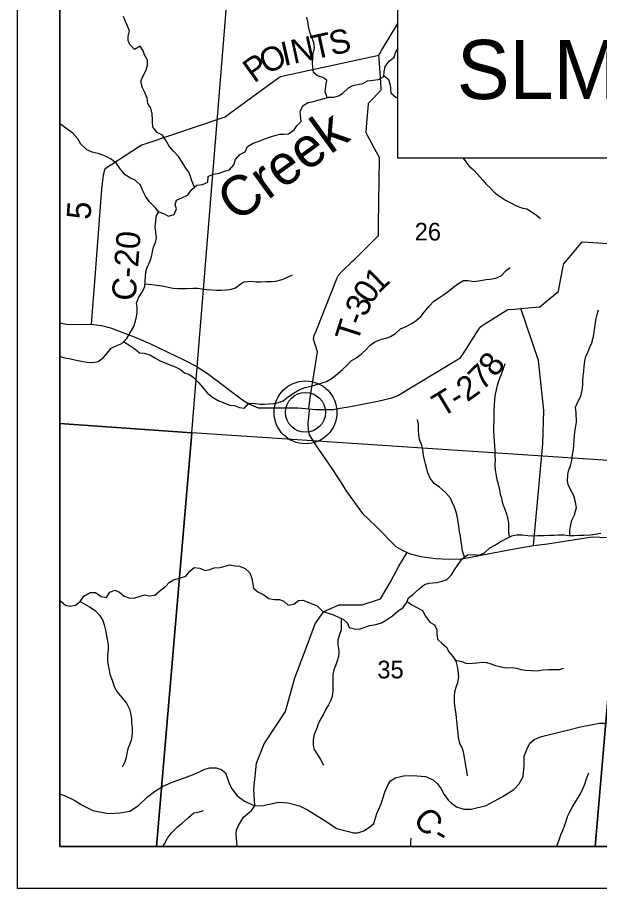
# Model space of a CAD drawing. Extents: x 0 to 34, y 0 to 22.
# Drawn here: x 23.417 to 24.795, y 14 to 16.062 of the extents above; entities that cross this region are included whole.
import ezdxf

# ---------------------------------------------------------------- set-up
doc = ezdxf.new("R2010")
doc.units = 0
for name, color, linetype in [('GM_X_Corporation', 7, 'Continuous'), ('GM_X_County_Road', 7, 'Continuous'), ('GM_X_County_Road_Text', 7, 'Continuous'), ('GM_X_Minor_River', 7, 'Continuous'), ('GM_X_Minor_River_Text', 7, 'Continuous'), ('GM_X_Section_Text', 7, 'Continuous'), ('GM_X_Township_Road', 7, 'Continuous'), ('GM_X_Township_Road_Text', 7, 'Continuous'), ('GM_X_Unincorporated', 7, 'Continuous'), ('GM_X_Unincorporated_Location', 7, 'Continuous'), ('SH_Data', 7, 'Continuous'), ('SH_Text', 7, 'Continuous')]:
    doc.layers.add(name, color=color, linetype=linetype)

msp = doc.modelspace()

# ---------------------------------------------------------------- linework, layer by layer
at = {"layer": 'GM_X_Corporation'}
for points in [[(26.1825, 18.4635), (26.1926, 18.5708), (26.207, 18.8068), (26.2271, 19.0168), (26.2277, 19.0233), (26.2281, 19.0286), (26.3029, 19.931), (25.7174, 19.9778), (25.482, 19.99), (25.2916, 20.0037), (25.117, 20.0172), (24.3889, 20.0736), (24.2296, 20.084), (23.8215, 20.1257), (23.5167, 20.1476), (23.5167, 14.1), (25.8273, 14.1), (25.8671, 14.5774), (25.9626, 15.7291)], [(24.9264, 15.7291), (24.8621, 15.0105), (23.8295, 15.0789), (23.9154, 16.1379), (24.3169, 16.1005)]]:
    msp.add_lwpolyline(points, dxfattribs=at)
for points in [[(23.5167, 16.1675), (23.5167, 15.1011), (23.8295, 15.0789), (23.9154, 16.1379)], [(23.5167, 15.1011), (23.5167, 14.1), (23.7459, 14.1), (23.8295, 15.0789)], [(23.7459, 14.1), (24.7842, 14.1), (24.8621, 15.0105), (23.8295, 15.0789)], [(24.7842, 14.1), (25.8293, 14.1), (25.8914, 14.8743), (25.8953, 14.9265), (24.8621, 15.0105)]]:
    msp.add_lwpolyline(points, close=True, dxfattribs=at)
at = {"layer": 'GM_X_County_Road'}
for points in [[(23.5923, 15.3361), (23.601, 15.4477), (23.6163, 15.6558), (23.6201, 15.69), (23.6247, 15.7045), (23.703, 15.7557), (23.7112, 15.7608), (23.7211, 15.7641), (23.9015, 15.8249), (23.9085, 15.8272), (23.9187, 15.8347), (24.0319, 15.9175), (24.0394, 15.9229), (24.0499, 15.9252), (24.2654, 15.9717), (24.2719, 15.9731), (24.2788, 15.9845), (24.3169, 16.0477)], [(23.5167, 15.3391), (23.5326, 15.3365), (23.5694, 15.3358), (23.5923, 15.3361)], [(23.5923, 15.3361), (23.6159, 15.3333), (23.6371, 15.3278), (23.6726, 15.3142), (23.6969, 15.3048), (23.7319, 15.2896), (23.8105, 15.2515), (23.8394, 15.2367), (23.8666, 15.2197), (23.9492, 15.1571), (23.9641, 15.1475), (23.9863, 15.1379), (24.0815, 15.1384), (24.1063, 15.1357), (24.1072, 15.1311), (24.1044, 15.102), (24.1048, 15.0862), (24.107, 15.0744), (24.124, 15.0483), (24.1609, 14.9942), (24.1843, 14.9585), (24.194, 14.9426), (24.2338, 14.8883), (24.2478, 14.8747), (24.267, 14.8565), (24.3124, 14.8097), (24.3292, 14.8003), (24.3395, 14.7958), (24.3475, 14.7923), (24.3709, 14.7863), (24.406, 14.7811), (24.4369, 14.7802), (24.4687, 14.7806), (24.4967, 14.7858), (24.5884, 14.8036), (24.6381, 14.8121), (24.6714, 14.8158), (24.7773, 14.8327), (24.8494, 14.8299)], [(23.5167, 14.2243), (23.5293, 14.2198), (23.5512, 14.2096), (23.5716, 14.1965), (23.595, 14.1848), (23.6314, 14.1775), (23.6592, 14.179), (23.6825, 14.1834), (23.7029, 14.1965), (23.7248, 14.2169), (23.7409, 14.23), (23.7598, 14.2417), (23.7832, 14.2519), (23.8124, 14.2621), (23.8313, 14.2694), (23.8474, 14.2767), (23.8605, 14.2826), (23.8722, 14.2855), (23.8873, 14.2856), (23.8989, 14.2821), (23.9093, 14.2739), (23.9142, 14.2603), (23.9179, 14.2485), (23.925, 14.2355), (23.9363, 14.22), (23.954, 14.207), (23.9786, 14.1956), (23.9992, 14.1963), (24.0094, 14.1994), (24.0349, 14.2049), (24.0569, 14.2031), (24.0845, 14.1958), (24.1031, 14.1863), (24.1424, 14.1617), (24.1728, 14.1425), (24.2005, 14.1352), (24.2122, 14.1323), (24.2224, 14.1323), (24.237, 14.1367), (24.2501, 14.1455), (24.2603, 14.1542), (24.2676, 14.1775), (24.2778, 14.2009), (24.2866, 14.2286), (24.2939, 14.2461), (24.2997, 14.2549), (24.3114, 14.2622), (24.3304, 14.2666), (24.3523, 14.268), (24.3829, 14.2651), (24.4004, 14.2578), (24.4106, 14.249), (24.4194, 14.2359), (24.4267, 14.2228), (24.4369, 14.2082), (24.4442, 14.2024), (24.4559, 14.1936), (24.4734, 14.1878), (24.4909, 14.1878), (24.5259, 14.1965), (24.5638, 14.217), (24.5916, 14.2345), (24.6047, 14.2476), (24.6135, 14.2651), (24.6164, 14.2914), (24.6164, 14.3133), (24.6222, 14.3293), (24.6295, 14.3439), (24.6397, 14.3526), (24.6572, 14.3599), (24.7024, 14.371), (24.7187, 14.3753), (24.7495, 14.3827), (24.7945, 14.3913), (24.8204, 14.3919)], [(23.9368, 14.1), (23.9345, 14.1287), (23.9356, 14.139), (23.9399, 14.1496), (23.9521, 14.1687), (23.9708, 14.1852), (23.9786, 14.1956)]]:
    msp.add_lwpolyline(points, dxfattribs=at)
at = {"layer": 'GM_X_Minor_River'}
for points in [[(23.8359, 15.6609), (23.8293, 15.6759), (23.8267, 15.6857), (23.8225, 15.6964), (23.8154, 15.7059), (23.8067, 15.7195), (23.7977, 15.7328), (23.7864, 15.7458), (23.7762, 15.7579), (23.7691, 15.7705), (23.7597, 15.7838), (23.7476, 15.7903), (23.7378, 15.8017), (23.7363, 15.8115), (23.7364, 15.821), (23.736, 15.8343), (23.7323, 15.8472), (23.7255, 15.859), (23.7237, 15.8715), (23.7173, 15.8863), (23.7124, 15.8958), (23.7091, 15.9106), (23.7137, 15.9227), (23.7209, 15.9363), (23.7247, 15.9484), (23.7248, 15.9609), (23.7176, 15.9735), (23.7143, 15.9833), (23.7071, 15.9944), (23.6939, 15.9865), (23.6825, 15.9982), (23.6788, 16.0077), (23.6788, 16.0183), (23.6819, 16.0308), (23.6778, 16.0403), (23.6725, 16.0525), (23.668, 16.0646)], [(24.1496, 15.8726), (24.1452, 15.8862), (24.1464, 15.8991), (24.1494, 15.9142), (24.1396, 15.9203), (24.1272, 15.9238), (24.1173, 15.9318), (24.1159, 15.9443), (24.1152, 15.9538), (24.1148, 15.964), (24.1171, 15.9769), (24.1195, 15.9901), (24.1184, 16.0034), (24.1127, 16.0171), (24.1086, 16.0277), (24.1053, 16.041), (24.1038, 16.0531), (24.1016, 16.063)], [(23.5167, 15.2594), (23.5292, 15.2567), (23.5391, 15.2551), (23.5561, 15.2512), (23.5686, 15.2489), (23.5818, 15.2462), (23.595, 15.2454), (23.6079, 15.2476), (23.6208, 15.2574), (23.6288, 15.2673), (23.6386, 15.2794), (23.6519, 15.2857), (23.6637, 15.2903), (23.6754, 15.3023), (23.6842, 15.3175), (23.6922, 15.3303), (23.696, 15.3432), (23.6983, 15.3534), (23.6999, 15.3637), (23.6999, 15.3762), (23.6988, 15.3856), (23.7034, 15.3989), (23.7122, 15.4117), (23.7179, 15.4254), (23.7194, 15.4371), (23.7195, 15.4492), (23.721, 15.4602), (23.7241, 15.4704), (23.731, 15.486), (23.7352, 15.4988), (23.7363, 15.5083), (23.739, 15.5182), (23.7432, 15.5295), (23.7459, 15.5405), (23.7445, 15.5541), (23.7426, 15.567), (23.7442, 15.5799), (23.7454, 15.592), (23.7514, 15.6019), (23.7624, 15.598), (23.7745, 15.5916), (23.7874, 15.5957), (23.7935, 15.6089), (23.7897, 15.6184), (23.7935, 15.6301), (23.806, 15.635), (23.8189, 15.6414), (23.8292, 15.6554), (23.8417, 15.6656), (23.8546, 15.6671), (23.8671, 15.6723), (23.8683, 15.686), (23.88, 15.6916), (23.894, 15.6938), (23.9069, 15.6983), (23.919, 15.7017), (23.9293, 15.7134), (23.9327, 15.7263), (23.943, 15.7376), (23.9555, 15.7444), (23.9616, 15.7569), (23.9745, 15.7644), (23.9889, 15.7696), (23.9999, 15.7742), (24.0154, 15.7794), (24.026, 15.7832), (24.0377, 15.7861), (24.0476, 15.7861), (24.0582, 15.7872), (24.0714, 15.7962), (24.0779, 15.8061), (24.0882, 15.8163), (24.0867, 15.8311), (24.086, 15.8405), (24.0932, 15.8538), (24.105, 15.8609), (24.1178, 15.8635), (24.1277, 15.8665), (24.1428, 15.8707), (24.1531, 15.8736), (24.1659, 15.8736), (24.1765, 15.877), (24.1864, 15.8826), (24.2004, 15.8955), (24.2107, 15.9015), (24.222, 15.9037), (24.2345, 15.9056), (24.2455, 15.912), (24.2588, 15.9142), (24.2713, 15.9153), (24.2841, 15.9228), (24.2846, 15.9334), (24.2873, 15.9459), (24.2964, 15.9592), (24.3081, 15.9682), (24.3123, 15.9807), (24.3169, 15.9877)], [(24.2842, 15.9251), (24.2947, 15.9156), (24.2992, 15.903), (24.2995, 15.8932), (24.3003, 15.8837), (24.3135, 15.873), (24.3169, 15.8717)], [(23.7511, 15.6013), (23.7428, 15.6125), (23.7296, 15.6258), (23.7198, 15.6395), (23.7134, 15.6517), (23.7078, 15.6653), (23.695, 15.6768), (23.684, 15.6821), (23.6719, 15.6901), (23.6595, 15.7042), (23.6509, 15.7163), (23.6388, 15.727), (23.6278, 15.7327), (23.6176, 15.7369), (23.6074, 15.7404), (23.5935, 15.7431), (23.5806, 15.7492), (23.567, 15.7625), (23.5595, 15.7751), (23.5478, 15.7884), (23.5312, 15.8002), (23.5214, 15.8074), (23.5167, 15.8106)], [(24.472, 15.7291), (24.4778, 15.7204), (24.4854, 15.7109), (24.4959, 15.7014), (24.5061, 15.6915), (24.5185, 15.6771), (24.5261, 15.6676), (24.5362, 15.6584), (24.5453, 15.6489), (24.5558, 15.6405), (24.5721, 15.6299), (24.583, 15.6245), (24.5966, 15.6169), (24.6095, 15.6119), (24.6227, 15.6092), (24.6351, 15.6016), (24.645, 15.594), (24.6548, 15.586)], [(23.6681, 15.2948), (23.6829, 15.2856), (23.6946, 15.2776), (23.7059, 15.2681), (23.7165, 15.2673), (23.7301, 15.2635), (23.7418, 15.2562), (23.7547, 15.2494), (23.7679, 15.2436), (23.7777, 15.2402), (23.7883, 15.2356), (23.8023, 15.2287), (23.8125, 15.2211), (23.8227, 15.2176), (23.8328, 15.2104), (23.8464, 15.1975), (23.8543, 15.1879), (23.8664, 15.1727), (23.8784, 15.1632), (23.8917, 15.1556), (23.9056, 15.1499), (23.9192, 15.1445), (23.9302, 15.1433), (23.9427, 15.1391), (23.954, 15.1375), (23.9646, 15.1493), (23.9798, 15.1484), (23.9911, 15.1465), (24.0013, 15.1468), (24.0119, 15.1476), (24.0233, 15.1487), (24.0346, 15.1509), (24.046, 15.1546), (24.0578, 15.1641), (24.0676, 15.1716), (24.0779, 15.1776), (24.0873, 15.1821), (24.0979, 15.1863), (24.1123, 15.1896), (24.1248, 15.193), (24.1358, 15.1967), (24.1483, 15.2005), (24.162, 15.2084), (24.1749, 15.2197), (24.187, 15.2295), (24.1969, 15.239), (24.2064, 15.2492), (24.2174, 15.2556), (24.2303, 15.2654), (24.242, 15.2763), (24.2508, 15.2861), (24.2625, 15.2941), (24.2788, 15.3008), (24.2898, 15.3034), (24.2996, 15.3068), (24.3114, 15.3143), (24.3235, 15.3253), (24.3368, 15.3309), (24.3504, 15.3377), (24.3603, 15.3445), (24.3713, 15.3547), (24.3793, 15.3645), (24.3911, 15.3785), (24.4025, 15.3906), (24.4154, 15.3996), (24.4252, 15.406), (24.437, 15.4143), (24.4495, 15.4245), (24.4605, 15.4328), (24.4726, 15.4396), (24.484, 15.4395), (24.498, 15.4376), (24.5131, 15.4398), (24.526, 15.4417), (24.5358, 15.4431), (24.5491, 15.4454), (24.5616, 15.451), (24.5733, 15.4631), (24.5832, 15.4706)], [(23.7187, 15.4316), (23.7345, 15.4302), (23.7466, 15.4283), (23.7591, 15.4267), (23.7739, 15.4236), (23.7848, 15.4217), (23.7965, 15.4209), (23.817, 15.4208), (23.8329, 15.4211), (23.8427, 15.4211), (23.8533, 15.4195), (23.8646, 15.4184), (23.8779, 15.4176), (23.8881, 15.4171), (23.8987, 15.4167), (23.91, 15.4174), (23.9206, 15.4185), (23.9331, 15.4223), (23.943, 15.4298), (23.9525, 15.4366), (23.9684, 15.4384), (23.9816, 15.4365), (23.9922, 15.4365), (24.0047, 15.4372), (24.0179, 15.4371), (24.0281, 15.4382), (24.0433, 15.4419), (24.0562, 15.4472), (24.0675, 15.4532)], [(24.7243, 14.8357), (24.7243, 14.8474), (24.7258, 14.8572), (24.7289, 14.872), (24.735, 14.8852), (24.74, 14.9023), (24.7374, 14.9152), (24.7337, 14.9296), (24.7201, 14.9562), (24.7187, 14.9664), (24.7195, 14.9785), (24.7214, 14.9888), (24.726, 15.0012), (24.7287, 15.0137), (24.7306, 15.0278), (24.7326, 15.0395), (24.7337, 15.0501), (24.7349, 15.0611), (24.7353, 15.0717), (24.7365, 15.0812), (24.7381, 15.0944), (24.7404, 15.1043), (24.7389, 15.1263), (24.7378, 15.1399), (24.7432, 15.1524), (24.75, 15.1656), (24.7535, 15.18), (24.7547, 15.1922), (24.7551, 15.2016), (24.7559, 15.2145), (24.7571, 15.224), (24.7583, 15.2365), (24.7598, 15.249), (24.7625, 15.26), (24.7675, 15.2713), (24.7717, 15.2819), (24.7762, 15.2918), (24.7805, 15.3073), (24.782, 15.3171), (24.7832, 15.3281), (24.7847, 15.3391), (24.7863, 15.3493), (24.789, 15.3592), (24.7924, 15.3702)], [(24.5818, 14.8327), (24.5798, 14.8437), (24.5802, 14.8536), (24.5798, 14.865), (24.5784, 14.8748), (24.5746, 14.8889), (24.5705, 14.8991), (24.5656, 14.912), (24.563, 14.9234), (24.5604, 14.9333), (24.5586, 14.9443), (24.5552, 14.9572), (24.5526, 14.9674), (24.5507, 14.9776), (24.5485, 14.9909), (24.5474, 15.0042), (24.5482, 15.0148), (24.5479, 15.0243), (24.5476, 15.0353), (24.5468, 15.0474), (24.5458, 15.061), (24.545, 15.0709), (24.5447, 15.083), (24.5448, 15.1198), (24.5453, 15.1319), (24.5461, 15.1456), (24.5465, 15.1562), (24.5477, 15.1664), (24.5504, 15.1804), (24.5534, 15.1918), (24.5565, 15.202), (24.5618, 15.2164), (24.5661, 15.2289), (24.5714, 15.2429)], [(24.4753, 14.7852), (24.4703, 14.799), (24.4688, 14.8112), (24.4673, 14.8214), (24.4651, 14.8343), (24.4632, 14.8449), (24.4614, 14.8578), (24.4599, 14.8673), (24.4585, 14.8783), (24.4558, 14.8885), (24.451, 14.9026), (24.4469, 14.9136), (24.4416, 14.9246), (24.4299, 14.9379), (24.4156, 14.9505), (24.4035, 14.9592), (24.3933, 14.9714), (24.3881, 14.9843), (24.3855, 14.9938), (24.3825, 15.0056), (24.3803, 15.0154), (24.378, 15.0249), (24.3762, 15.0389), (24.3743, 15.0496), (24.3687, 15.0628), (24.3665, 15.0746), (24.3662, 15.0856), (24.3658, 15.0985), (24.3636, 15.1106)], [(24.0117, 14.6867), (24.025, 14.6847), (24.0367, 14.6847), (24.0473, 14.6801), (24.0578, 14.6706), (24.0707, 14.6736), (24.0821, 14.6819), (24.0923, 14.6826), (24.1025, 14.6791), (24.1123, 14.6753), (24.1259, 14.6696), (24.1387, 14.657), (24.1519, 14.6517), (24.1652, 14.6478), (24.178, 14.6421), (24.1878, 14.6375), (24.1976, 14.628), (24.2018, 14.6181), (24.2142, 14.6151), (24.2263, 14.6139), (24.2392, 14.6191), (24.2506, 14.6229), (24.2653, 14.6251), (24.2782, 14.6288), (24.2907, 14.6364), (24.3044, 14.6454), (24.3169, 14.6567), (24.3294, 14.6658), (24.3378, 14.6764), (24.342, 14.6885), (24.3526, 14.696), (24.3674, 14.7096), (24.3799, 14.7198), (24.3902, 14.7228), (24.4, 14.7239), (24.4098, 14.725), (24.4223, 14.728), (24.4322, 14.7313), (24.4443, 14.7427), (24.4516, 14.7544), (24.4603, 14.7672), (24.4691, 14.7809), (24.482, 14.7899), (24.496, 14.791), (24.5103, 14.7894), (24.5221, 14.7947), (24.535, 14.8068), (24.5482, 14.8135), (24.5604, 14.8218), (24.574, 14.829), (24.5873, 14.8354), (24.5971, 14.8376), (24.6115, 14.8376), (24.6251, 14.836), (24.635, 14.8352), (24.6482, 14.8359), (24.663, 14.8358), (24.6762, 14.8366), (24.6868, 14.8369), (24.697, 14.8372), (24.7102, 14.8372), (24.722, 14.8356), (24.7348, 14.836), (24.7462, 14.8367), (24.7572, 14.837), (24.773, 14.8377), (24.7844, 14.8388), (24.7976, 14.8418)], [(23.5167, 14.6828), (23.5203, 14.6798), (23.5308, 14.6707), (23.5411, 14.6684), (23.5543, 14.671), (23.5653, 14.6796), (23.5741, 14.6925), (23.5885, 14.7012), (23.6017, 14.7007), (23.6145, 14.6916), (23.6278, 14.6893), (23.6357, 14.7014), (23.6475, 14.7066), (23.6581, 14.702), (23.6683, 14.6933), (23.6819, 14.6872), (23.6947, 14.6886), (23.7046, 14.6916), (23.7171, 14.6954), (23.7284, 14.6931), (23.7416, 14.6945), (23.7542, 14.7055), (23.7663, 14.7141), (23.7769, 14.7255), (23.7864, 14.7311), (23.8004, 14.7345), (23.8152, 14.7393), (23.8247, 14.7518), (23.8353, 14.7605), (23.8486, 14.7582), (23.8599, 14.7532), (23.8724, 14.7554), (23.8822, 14.7596), (23.8966, 14.7603), (23.9087, 14.7636), (23.919, 14.7662), (23.9318, 14.7643), (23.9424, 14.7631), (23.9556, 14.7574), (23.9669, 14.7475), (23.9718, 14.7342), (23.9736, 14.7209), (23.9751, 14.7111), (23.9857, 14.7023), (23.9997, 14.6958), (24.0117, 14.6867)], [(23.5654, 14.6798), (23.5766, 14.6732), (23.5876, 14.6667), (23.6004, 14.6583), (23.6106, 14.6469), (23.6185, 14.6343), (23.6222, 14.6241), (23.6252, 14.612), (23.6278, 14.5987), (23.6296, 14.5858), (23.6311, 14.5763), (23.6311, 14.5653), (23.6299, 14.5528), (23.6299, 14.5399), (23.6317, 14.5282), (23.6339, 14.5172), (23.6358, 14.5077), (23.6407, 14.4933), (23.6459, 14.4785), (23.6508, 14.4675), (23.6745, 14.439), (23.682, 14.4249), (23.6842, 14.4154), (23.6865, 14.4021), (23.6868, 14.3912), (23.6883, 14.3813), (23.6886, 14.3684), (23.687, 14.354), (23.6821, 14.3404), (23.6783, 14.3306), (23.6756, 14.3196), (23.674, 14.3101), (23.6706, 14.2999), (23.6649, 14.2874)], [(24.3389, 14.6794), (24.3502, 14.6714), (24.3635, 14.6645), (24.3755, 14.658), (24.3823, 14.6447), (24.3928, 14.6311), (24.4042, 14.6246), (24.4094, 14.6128), (24.4098, 14.6033), (24.4109, 14.5908), (24.421, 14.5813), (24.4331, 14.571), (24.4368, 14.5615), (24.4478, 14.5486), (24.4542, 14.5387), (24.4579, 14.5255), (24.4594, 14.516), (24.4605, 14.5016), (24.4581, 14.4868), (24.4543, 14.4758), (24.4512, 14.4656), (24.4504, 14.4546), (24.4508, 14.4413), (24.4522, 14.4269), (24.4541, 14.4137), (24.4556, 14.4034), (24.4566, 14.3905), (24.4577, 14.3799), (24.4588, 14.3686), (24.4599, 14.3579), (24.4629, 14.3435), (24.4685, 14.3337), (24.4715, 14.3234), (24.4741, 14.3105), (24.4756, 14.3007), (24.4775, 14.2904), (24.4793, 14.2794), (24.4815, 14.2669)], [(24.1833, 14.6396), (24.1832, 14.622), (24.1828, 14.6125), (24.1786, 14.5993), (24.1748, 14.5883), (24.1751, 14.5781), (24.1766, 14.5686), (24.1777, 14.5591), (24.1765, 14.5492), (24.1738, 14.5394), (24.1693, 14.5277), (24.1658, 14.5175), (24.1631, 14.5072), (24.163, 14.4807), (24.1634, 14.469), (24.1614, 14.4546), (24.1576, 14.4447), (24.153, 14.4349), (24.1469, 14.4251), (24.1412, 14.4129), (24.1359, 14.4031), (24.1287, 14.3899), (24.1252, 14.38), (24.1187, 14.3649), (24.1164, 14.352), (24.1171, 14.3391), (24.1193, 14.3293), (24.128, 14.316), (24.1344, 14.3057), (24.1415, 14.2924)], [(24.4528, 14.5409), (24.4689, 14.5375), (24.4799, 14.533), (24.4942, 14.5333), (24.5045, 14.5344), (24.517, 14.5358), (24.5268, 14.5351), (24.5374, 14.532), (24.5483, 14.5282), (24.5615, 14.5247), (24.5736, 14.5228), (24.588, 14.5231), (24.5982, 14.5215), (24.6084, 14.5185), (24.6194, 14.5173), (24.6334, 14.5165), (24.6474, 14.5153), (24.6599, 14.5175), (24.6739, 14.5186), (24.6871, 14.5189), (24.6996, 14.5189), (24.7095, 14.5219)], [(24.6928, 14.1), (24.6943, 14.1028), (24.6985, 14.1134), (24.7031, 14.127), (24.7076, 14.1372), (24.7118, 14.1486), (24.7157, 14.1599), (24.7191, 14.1705), (24.7241, 14.1815), (24.7313, 14.1951), (24.7378, 14.2057), (24.7446, 14.2163), (24.7503, 14.2261), (24.7553, 14.2363), (24.7595, 14.2469), (24.7641, 14.2598), (24.7691, 14.2738)], [(23.7609, 14.1), (23.7648, 14.1063), (23.772, 14.1191), (23.7816, 14.132), (23.7952, 14.1459), (23.8066, 14.1546), (23.8214, 14.1682), (23.8343, 14.1791), (23.8476, 14.1814), (23.857, 14.1847)], [(24.3481, 14.1), (24.3482, 14.1098), (24.3486, 14.1192)]]:
    msp.add_lwpolyline(points, dxfattribs=at)
at = {"layer": 'GM_X_Township_Road'}
for points in [[(24.2431, 15.8035), (24.2474, 15.8567), (24.2476, 15.8591), (24.2585, 15.8707), (24.2774, 15.8908), (24.278, 15.8914), (24.2767, 15.9088), (24.2726, 15.9638), (24.2719, 15.9731)], [(24.2716, 15.5739), (24.2738, 15.7273), (24.2738, 15.7308), (24.2667, 15.7438), (24.2447, 15.7841), (24.2419, 15.7893), (24.243, 15.8017), (24.2431, 15.8035)], [(24.2135, 15.4889), (24.2699, 15.5442), (24.2712, 15.5454), (24.2714, 15.562), (24.2715, 15.5712), (24.2716, 15.5739)], [(24.1063, 15.1357), (24.1234, 15.1338), (24.1642, 15.134), (24.1808, 15.1374), (24.2049, 15.1412), (24.27, 15.1542), (24.3032, 15.1619), (24.3172, 15.1677), (24.458, 15.2523), (24.465, 15.256), (24.4714, 15.2659), (24.5091, 15.324), (24.5136, 15.3309), (24.5234, 15.337), (24.5737, 15.3683), (24.5777, 15.3707), (24.5928, 15.3721), (24.6081, 15.3735), (24.6518, 15.3774), (24.6535, 15.3776), (24.6675, 15.389), (24.6904, 15.4078), (24.6972, 15.4133), (24.6993, 15.4242), (24.7088, 15.4727), (24.7101, 15.479), (24.7185, 15.4893), (24.75, 15.5274), (24.7533, 15.5314), (24.7678, 15.5304), (24.8467, 15.525)], [(24.1063, 15.1357), (24.1099, 15.1617), (24.119, 15.2211), (24.1267, 15.2707), (24.1176, 15.3008), (24.119, 15.3092), (24.1227, 15.3183), (24.1738, 15.4462), (24.1763, 15.4524), (24.1847, 15.4606), (24.2109, 15.4863), (24.2135, 15.4889)], [(24.6381, 14.8121), (24.6604, 15.0533), (24.6625, 15.1316), (24.6504, 15.2502), (24.6081, 15.3735)], [(23.9786, 14.1956), (23.9759, 14.2354), (23.9828, 14.2968), (24.0009, 14.3423), (24.051, 14.4196), (24.0737, 14.4992), (24.101, 14.5719), (24.1215, 14.6265), (24.1419, 14.6561), (24.1783, 14.672), (24.2329, 14.672), (24.2761, 14.6856), (24.2988, 14.7243), (24.3193, 14.763), (24.3395, 14.7958)]]:
    msp.add_lwpolyline(points, dxfattribs=at)
at = {"layer": 'GM_X_Unincorporated'}
for radius in [0.0744, 0.0472]:
    msp.add_circle((24.0985, 15.1274), radius, dxfattribs=at)
at = {"layer": 'GM_X_Unincorporated_Location'}
msp.add_line((24.0985, 15.1274), (24.0985, 15.1274), dxfattribs=at)
at = {"layer": 'SH_Data'}
for points in [[(23.4167, 21), (30.4167, 21), (30.4167, 14), (23.4167, 14)], [(23.5167, 20.9), (30.3167, 20.9), (30.3167, 14.1), (23.5167, 14.1)], [(24.3169, 16.5691), (26.1924, 16.5691), (26.1924, 15.7291), (24.3169, 15.7291)]]:
    msp.add_lwpolyline(points, close=True, dxfattribs=at)

# ---------------------------------------------------------------- texts
at = {"layer": 'GM_X_County_Road_Text'}
for s, height, rotation, p in [('T', 0.0568, 12.2992, (24.1193, 15.9628)), ('S', 0.0568, 12.3012, (24.1608, 15.9719)), ('I', 0.0568, 12.7659, (24.0478, 15.947)), ('N', 0.0568, 12.3237, (24.0704, 15.9522)), ('O', 0.0568, 25.3463, (24.0057, 15.9267)), ('P', 0.0568, 35.72, (23.9769, 15.9057)), ('5', 0.0568, 85.917, (23.5894, 15.5825)), ('C-20', 0.05682, 85.5458, (23.696, 15.3901)), ('C', 0.0568, 312.4491, (24.3504, 14.1606)), ('-', 0.0568, 330.9195, (24.3975, 14.1138))]:
    msp.add_text(s, height=height, rotation=rotation, dxfattribs=at).set_placement(p)
at = {"layer": 'GM_X_Minor_River_Text'}
msp.add_text('Creek', height=0.0947, rotation=36.0028, dxfattribs=at).set_placement((23.9349, 15.5752))
at = {"layer": 'GM_X_Section_Text'}
for s, p in [('26', (24.3571, 15.5343)), ('35', (24.2687, 14.4976))]:
    msp.add_text(s, height=0.04186, rotation=0, dxfattribs=at).set_placement(p)
at = {"layer": 'GM_X_Township_Road_Text'}
for s, rotation, p in [('1', 44.1819, (24.2715, 15.4072)), ('0', 55.9098, (24.254, 15.3808)), ('3', 68.1979, (24.2427, 15.3514)), ('T', 72.2182, (24.2215, 15.2905)), ('-', 68.1977, (24.2341, 15.3299)), ('8', 52.8019, (24.5484, 15.2085)), ('7', 44.1201, (24.517, 15.1771)), ('2', 35.4384, (24.4813, 15.1508)), ('T', 31.0975, (24.421, 15.1142)), ('-', 31.0975, (24.4574, 15.1362))]:
    msp.add_text(s, height=0.0568, rotation=rotation, dxfattribs=at).set_placement(p)
at = {"layer": 'SH_Text'}
msp.add_text('SLM 10.44', height=0.14, dxfattribs=at).set_placement((24.4569, 15.8691))

doc.saveas('drawing.dxf')
